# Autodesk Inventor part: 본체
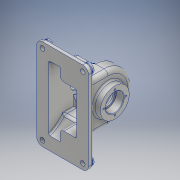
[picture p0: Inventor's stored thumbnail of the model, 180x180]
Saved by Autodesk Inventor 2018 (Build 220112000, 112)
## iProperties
Created: 2024-01
Part Number: 본체
Material: 알루미늄 6061
Document SubType Name: Modeling
Designer: na
Density: 2.7 g/cm^3
Appearance: 알루미늄 - 평지
Mass: 738.884 g
Surface Area: 909.108 cm^2
Volume: 273.661 cm^3
Author: na
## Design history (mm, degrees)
sketch "스케치1"
  geometry: L1 (-39, -88)-(39, -88); L2 (50, -77)-(50, 77); L3 (39, 88)-(-39, 88); L4 (-50, 77)-(-50, -77); L5 (-50, -88)-(50, 88); L6 (50, -88)-(-50, 88); A1 r 11 centre (39, 77) between (50, 77) and (39, 88); A2 r 11 centre (39, -77) between (39, -88) and (50, -77); A3 r 11 centre (-39, -77) between (-50, -77) and (-39, -88); A4 r 11 centre (-39, 77) between (-39, 88) and (-50, 77); 1 further point
  constraints: 12 end point, 8 point on circle, 8 point on line, 8 tangent, 4 centre point, 3 equal radius, 2 midpoint, 2 parallel, 1 horizontal, 1 perpendicular
  dimensions: "d2" = 11 radius of A1; "d3" = 154 distance of A2.centre A1.centre; "d4" = 78 distance of A4.centre A1.centre
extrude "돌출1" new body sketch "스케치1" distance "d5" = 9; taper "d6" = 0 deg
sketch "스케치2"
  geometry: L1 (0, 0)-(47, 0); L2 (47, 0)-(47, 46); L3 (47, 46)-(0, 46); L4 (0, 46)-(0, 0); L5 (47, 0)-(47, -46); L6 (47, -46)-(0, -46); L7 (0, -46)-(0, 0); A1 r 46 centre (47, 0) between (47, -46) and (47, 46)
  constraints: 14 end point, 3 perpendicular, 2 horizontal, 2 point on circle, 2 point on line, 1 centre point, 1 coincident, 1 tangent, 1 vertical
  dimensions: "d7" = 47 distance of L1.start L1.end; "d8" = 92 diameter of A1
extrude "돌출2" join sketch "스케치2" distance "d9" = 32; taper "d10" = 0 deg
sketch "스케치3"
  geometry: L1 (-9, -77)-(-9, 77) reference; L2 (-9, 0)-(39, 0); L3 (-9, -67.882)-(-9, 67.882); A1 r 72 centre (-33, 0) between (-9, -67.882) and (-9, 67.882); 3 further points
  constraints: 4 end point, 4 point on circle, 2 coincident, 2 point on line, 1 centre point, 1 collinear, 1 horizontal, 1 horizontal alignment, 1 midpoint
  dimensions: "d11" = 48 distance of L2.start L2.end; "d12" = 72 radius of A1
extrude "돌출3" join sketch "스케치3" distance "d13" = 32; taper "d14" = 0 deg
sketch "스케치4"
  geometry: L1 (-77, 0)-(77, 0) reference; L2 (77, 0)-(77, -9) reference; L3 (-77, -9)-(77, -9) reference; L4 (-77, 0)-(-77, -9) reference; L5 (0, -9)-(-46, -9); L6 (0, -9)-(46, -9); L7 (0, -9)-(0, 47); L8 (0, 47)-(-46, 47); L9 (0, 47)-(46, 47); L10 (-46, 0)-(-46, 47) reference; L11 (-46, 47)-(-46, -9); L12 (46, 47)-(46, 0) reference; L13 (46, 47)-(46, -9)
  constraints: 14 end point, 4 point on line, 2 horizontal alignment, 2 vertical, 1 horizontal, 1 midpoint
  dimensions: "d23" = 56 distance of L5.start L7.end
extrude "돌출4" join sketch "스케치4" distance "d24" = 32; taper "d25" = 0 deg
node "작업 평면1"
sketch "스케치5"
  geometry: L1 (-77, -9)-(77, -9) reference; L2 (0, -9)-(0, 47); C1 r 28 at (0, 47); 1 further point
  constraints: 2 end point, 1 centre point, 1 coincident, 1 midpoint, 1 vertical
  dimensions: "d27" = 56 distance of L2.start L2.end; "d28" = 56 diameter of C1
extrude "돌출5" join sketch "스케치5" distance "d29" = 90; taper "d30" = 0 deg
node "작업 평면2"
feature "쉘1" dims "d64" = 5
sketch "스케치14"
  geometry: L1 (34, 22.131)-(34, 42) reference; L2 (12, 22.131)-(34, 22.131) reference; L3 (12, 143.869)-(12, 22.131) reference; L4 (34, 143.869)-(12, 143.869) reference; L5 (34, 124)-(34, 143.869) reference; L6 (66, 124)-(34, 124) reference; L7 (66, 42)-(66, 124) reference; L8 (34, 42)-(66, 42) reference; L9 (-6, 160)-(-6, 6) reference; L10 (0, 0)-(78, 0) reference; L11 (84, 6)-(84, 160) reference; L12 (78, 166)-(0, 166) reference; A1 r 6 centre (0, 6) between (-6, 6) and (0, 0) reference; A2 r 6 centre (78, 6) between (78, 0) and (84, 6) reference; A3 r 6 centre (78, 160) between (84, 160) and (78, 166) reference; A4 r 6 centre (0, 160) between (0, 166) and (-6, 160) reference; 1 further point
extrude "돌출8" join sketch "스케치14" stored distance "d65" = 22; taper "d66" = 0 deg
sketch "스케치15"
  geometry: L1 (-36, -28.991)-(118, -28.991) reference; L2 (-15.124, -7.889)-(97.124, -7.889); L3 (94.674, -12.889)-(-12.674, -12.889); A1 r 72 centre (41, -52.991) between (-5, 2.399) and (-22.992, -19.991) reference; A2 r 72 centre (41, -52.991) between (-15.124, -7.889) and (-26.882, -28.991); A3 r 72 centre (41, -52.991) between (108.882, -28.991) and (97.124, -7.889); A4 r 67 centre (41, -52.991) between (103.554, -28.991) and (94.674, -12.889); A5 r 67 centre (41, -52.991) between (-12.674, -12.889) and (-21.554, -28.991); 1 further point
  constraints: 8 point on circle, 4 centre point, 4 end point, 4 point on line, 1 coincident, 1 horizontal
  dimensions: "d67" = 72 radius of A3; "d68" = 72 radius of A2; "d69" = 21.10107 distance between parallel lines of L2 L1; "d71" = 5 distance between parallel lines of L2 L3; "d72" = 67 radius of A5; "d73" = 67 radius of A4
extrude "돌출9" cut sketch "스케치15" distance "d74" = 22; taper "d75" = 0 deg
sketch "스케치17"
  geometry: C1 r 28 at (0, 0) reference; 1 further point
extrude "돌출10" join sketch "스케치17" distance "d83" = 18; taper "d84" = 0 deg
sketch "스케치18"
  geometry: C1 r 28 at (0, 0) reference; 2 further points
  constraints: 1 coincident
hole "구멍2" sketch "스케치18" at (0, 0) diameter "d85" = 29; stored, may be unused: countersink angle "d89" = 90 deg, drill point angle "d91" = 118 deg; dims "d86" = 6, "d87" = 35, "d88" = 15, "d90" = 18
fillet "모깎기1" dims "d92" = 8
fillet "모깎기2" dims "d93" = 8
fillet "모깎기3" dims "d94" = 8
fillet "모깎기4" dims "d95" = 3
fillet "모깎기5" dims "d96" = 3
fillet "모깎기6" dims "d97" = 3
fillet "모깎기7" dims "d98" = 3
sketch "스케치21"
  geometry: C1 r 9 at (-39, -77); C2 r 9 at (39, -77); A1 r 11 centre (-39, -77) between (-50, -77) and (-39, -88) reference; A2 r 11 centre (39, -77) between (39, -88) and (50, -77) reference; 1 further point
  constraints: 2 centre point, 2 coincident
  dimensions: "d99" = 18 diameter of C1; "d100" = 18 diameter of C2
extrude "돌출11" join sketch "스케치21" distance "d101" = 4; taper "d102" = 0 deg
sketch "스케치22"
  geometry: C1 r 9 at (0, 0) reference; C2 r 9 at (-78, 0) reference; 3 further points
  constraints: 2 coincident
hole "구멍3" sketch "스케치22" at (0, 0), (-78, 0) diameter "d103" = 9; stored, may be unused: countersink angle "d107" = 90 deg, drill point angle "d109" = 118 deg; dims "d104" = 6, "d105" = 35, "d106" = 15, "d108" = 18
fillet "모깎기8" dims "d110" = 3
node "작업 평면4"
sketch "스케치23"
  geometry: L1 (0, 0)-(17, 0); C1 r 6 at (17, 0); 1 further point
  constraints: 2 coincident, 2 end point, 1 centre point, 1 horizontal
  dimensions: "d112" = 17 distance of L1.start L1.end; "d114" = 12 diameter of C1
extrude "돌출12" join sketch "스케치23" stored distance "d115" = 4; taper "d116" = 0 deg
sketch "스케치25"
  geometry: C1 r 6 at (0, 0) reference; 2 further points
  constraints: 1 coincident
hole "구멍4" sketch "스케치25" at (0, 0) diameter "d117" = 5.188; stored, may be unused: countersink angle "d121" = 90 deg, drill point angle "d123" = 118 deg; dims "d118" = 100, "d119" = 8, "d120" = 2, "d122" = 16
node "작업 평면5"
sketch "스케치26"
  geometry: L1 (0, 0)-(-17, 0); C1 r 6 at (-17, 0)
  constraints: 2 end point, 1 centre point, 1 coincident, 1 horizontal
  dimensions: "d125" = 17 distance of L1.start L1.end; "d126" = 12 diameter of C1
extrude "돌출13" join sketch "스케치26" stored distance "d127" = 0; taper "d128" = 0 deg
sketch "스케치27"
  geometry: 3 further points
  constraints: 1 other
  dimensions: "d129" = 17 distance of point (17, 0) point (0, 0); "d130" = 6 distance of point (0, 6) point (0, 0)
hole "구멍5" sketch "스케치27" at (0, 0) diameter "d131" = 5.188; stored, may be unused: countersink angle "d135" = 90 deg, drill point angle "d137" = 118 deg; dims "d132" = 12, "d133" = 8, "d134" = 2, "d136" = 12
sketch "스케치28" dims "d138" = 43
  geometry: L1 (0, 0)-(0, 21.5); C1 r 17.5 at (0, 0) reference; C2 r 28 at (0, 0) reference; 2 further points
  constraints: 2 coincident, 2 end point, 1 vertical, 1 vertical alignment, 2 other
hole "구멍6" sketch "스케치28" at (0, 21.5) diameter "d139" = 3.242; stored, may be unused: countersink angle "d143" = 90 deg, drill point angle "d145" = 118 deg; dims "d140" = 8, "d141" = 8, "d142" = 2, "d144" = 10
chamfer "모따기1" distance "d149" = 1; stored, may be unused: second distance "d150" = 2, angle "d151" = 45 deg
fillet "모깎기9" dims "d152" = 0.6
sketch "스케치29"
  geometry: C1 r 28 at (0, 0) reference; C2 r 28 at (0, 0); 1 further point
  constraints: 1 centre point, 1 coincident, 1 concentric
extrude "돌출14" join sketch "스케치29" distance "d153" = 18; taper "d154" = 0 deg
chamfer "모따기2" distance "d155" = 1; stored, may be unused: second distance "d156" = 2, angle "d157" = 45 deg
fillet "모깎기10" dims "d158" = 0.6
fillet "모깎기11" dims "d159" = 3
fillet "모깎기12" dims "d160" = 3
fillet "모깎기13" dims "d161" = 8
node "솔리드1"
mirror "미러1"
mirror "미러2"
pattern_circular "원형 패턴1" dims angle "d147" = 360 deg
mirror "미러4"
node "투영된 루프2"
node "투영된 루프3"
node "투영된 루프4"
node "투영된 루프5"
other parameters: "d26" = 13, "d31" = -5, "d111" = -106, "d124" = -88
